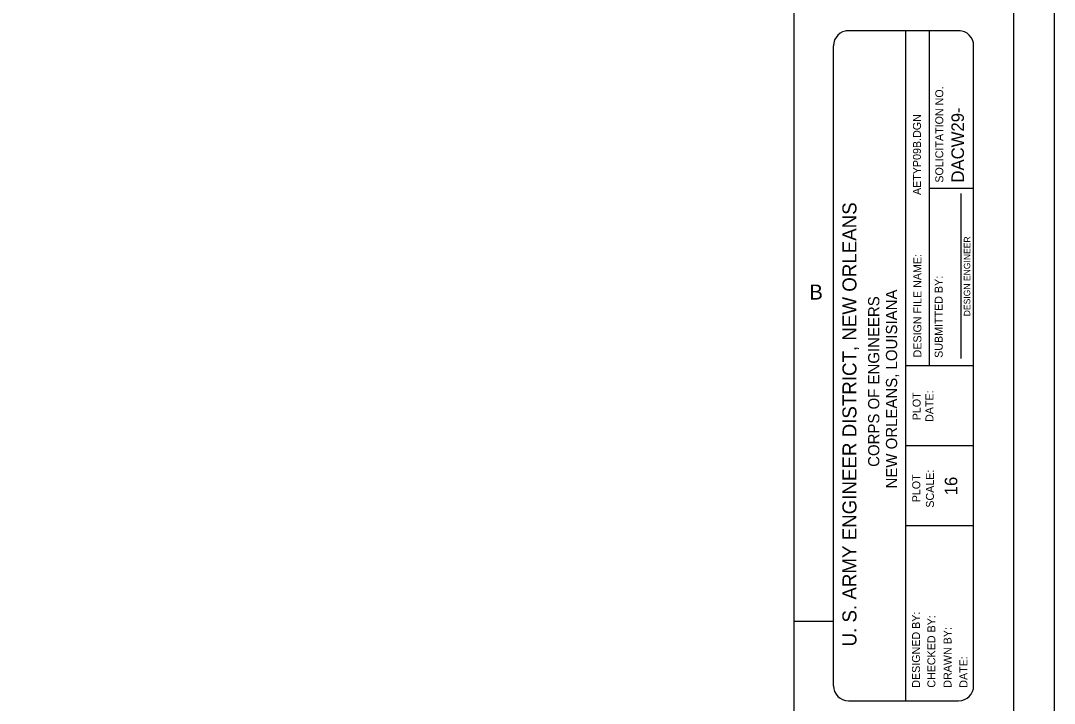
# Model space of a CAD drawing. Extents: x 22369.6 to 22428.3, y 22369.6 to 22415.
# Drawn here: x 22411.06 to 22428.29, y 22379.91 to 22391.29 of the extents above; entities that cross this region are included whole.
import ezdxf

# ---------------------------------------------------------------- set-up
doc = ezdxf.new("R2010")
doc.units = 0
for name, color, linetype in [('Level 1', 7, 'Continuous'), ('Level 10', 7, 'Continuous'), ('Level 2', 7, 'Continuous'), ('Level 7', 7, 'Continuous'), ('Level 9', 7, 'Continuous')]:
    doc.layers.add(name, color=color, linetype=linetype)

msp = doc.modelspace()

# ---------------------------------------------------------------- linework, layer by layer
at = {"layer": 'Level 1'}
for p, q in [((22426.72, 22391.12), (22424.816, 22391.12)), ((22425.808, 22391.12), (22425.808, 22379.952))]:
    msp.add_line(p, q, dxfattribs=at)
msp.add_lwpolyline([(22369.621, 22414.955), (22428.288, 22414.955), (22428.288, 22369.621), (22369.621, 22369.621)], close=True, dxfattribs=at)
for points in [[(22426.694, 22391.12), (22424.858, 22391.12)], [(22424.608, 22380.202), (22424.608, 22390.87)], [(22426.944, 22380.202), (22426.944, 22390.87)], [(22424.858, 22379.952), (22426.694, 22379.952)]]:
    msp.add_lwpolyline(points, dxfattribs=at)
for centre, start, end in [((22424.858, 22390.87), 90, 180), ((22426.694, 22390.87), 0, 90), ((22424.858, 22380.202), 180, 270), ((22426.694, 22380.202), 270, 0)]:
    msp.add_arc(centre, 0.25, start, end, dxfattribs=at)
at = {"layer": 'Level 10'}
msp.add_line((22423.952, 22381.28), (22424.608, 22381.28), dxfattribs=at)
at = {"layer": 'Level 2'}
for p, q in [((22426.202, 22391.12), (22426.202, 22385.536)), ((22426.944, 22388.491), (22426.202, 22388.491)), ((22426.736, 22385.657), (22426.736, 22388.405)), ((22426.944, 22385.536), (22425.808, 22385.536)), ((22426.944, 22384.203), (22425.808, 22384.203)), ((22426.944, 22382.869), (22425.808, 22382.869))]:
    msp.add_line(p, q, dxfattribs=at)
at = {"layer": 'Level 9'}
msp.add_line((22427.616, 22370.288), (22427.616, 22414.288), dxfattribs=at)
msp.add_lwpolyline([(22423.952, 22370.288), (22423.952, 22414.288)], dxfattribs=at)

# ---------------------------------------------------------------- texts
at = {"layer": 'Level 1'}
for s, height, p in [('SOLICITATION NO.', 0.13334, (22426.438, 22388.588)), ('AETYP09B.DGN', 0.13334, (22426.066, 22388.382)), ('U. S. ARMY ENGINEER DISTRICT, NEW ORLEANS', 0.23333, (22424.991, 22380.858)), ('DESIGN ENGINEER', 0.10666, (22426.887, 22386.361)), ('DESIGN FILE NAME:', 0.13334, (22426.073, 22385.675)), ('SUBMITTED BY:', 0.13334, (22426.428, 22385.668)), ('PLOT', 0.1333, (22426.06, 22384.628)), ('DATE:', 0.1333, (22426.273, 22384.6)), ('SCALE:', 0.1333, (22426.282, 22383.171)), ('PLOT', 0.1333, (22426.054, 22383.261)), ('DESIGNED BY:', 0.13334, (22426.05, 22380.17)), ('CHECKED BY:', 0.13334, (22426.306, 22380.17)), ('DRAWN BY:', 0.1333, (22426.575, 22380.17)), ('DATE:', 0.1333, (22426.841, 22380.17))]:
    msp.add_text(s, height=height, rotation=90, dxfattribs=at).set_placement(p)
msp.add_text('B', height=0.25, dxfattribs=at).set_placement((22424.208, 22386.64))
at = {"layer": 'Level 7'}
for s, height, p in [('DACW29-', 0.208, (22426.782, 22388.59)), ('NEW ORLEANS, LOUISIANA', 0.18667, (22425.669, 22383.491)), ('CORPS OF ENGINEERS', 0.18667, (22425.372, 22383.851)), ('16', 0.208, (22426.671, 22383.377))]:
    msp.add_text(s, height=height, rotation=90, dxfattribs=at).set_placement(p)

doc.saveas('drawing.dxf')
